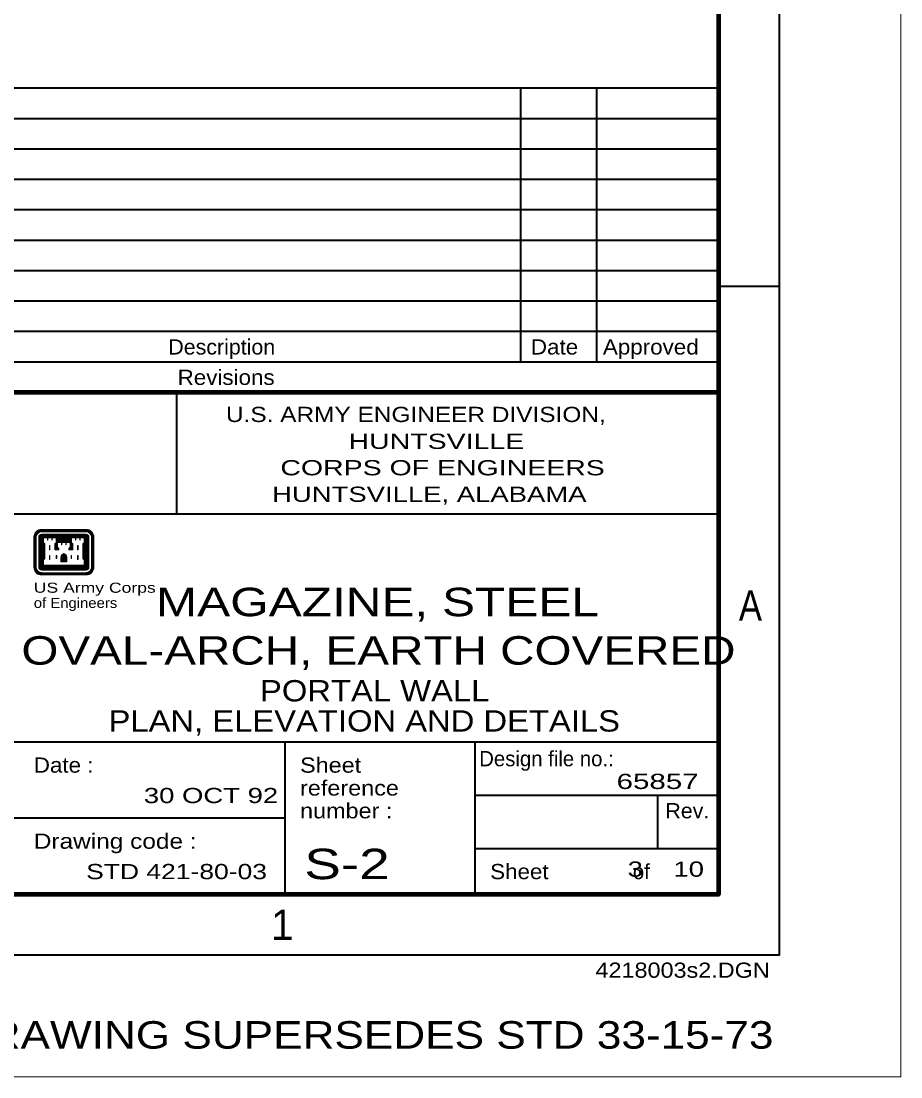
# Model space of a CAD drawing. Extents: x -22.3 to 19.7, y -11.8 to 18.2.
# Drawn here: x 12.46 to 19.69, y -11.84 to -3.16 of the extents above; entities that cross this region are included whole.
import ezdxf
from ezdxf.enums import TextEntityAlignment as Align

# ---------------------------------------------------------------- set-up
doc = ezdxf.new("R2010")
doc.units = 0
doc.header["$LTSCALE"] = 0.05
doc.layers.add('1', color=7, linetype='Continuous', lineweight=13)
doc.layers.add('2', color=7, linetype='Continuous', lineweight=13)

msp = doc.modelspace()

# ---------------------------------------------------------------- linework, layer by layer
at = {"layer": '1', "lineweight": 40}
for p, q in [((18.19058, -3.71469), (10.19058, -3.71469)), ((16.56558, -3.71469), (16.56558, -5.96469)), ((17.19058, -3.71469), (17.19058, -5.96469)), ((18.19058, -3.96469), (10.19058, -3.96469)), ((18.19058, -4.21469), (10.19058, -4.21469)), ((18.19058, -4.46469), (10.19058, -4.46469)), ((18.19058, -4.71469), (10.19058, -4.71469)), ((18.19058, -4.96469), (10.19058, -4.96469)), ((18.19058, -5.21469), (10.19058, -5.21469)), ((18.19058, -5.33969), (18.69058, -5.33969)), ((18.19058, -5.46469), (10.19058, -5.46469)), ((18.19058, -5.71469), (10.19058, -5.71469)), ((18.19058, -5.96469), (10.19058, -5.96469)), ((13.73858, -6.21469), (13.73858, -7.21469)), ((18.19058, -7.21469), (10.19058, -7.21469)), ((18.19058, -9.08969), (10.19058, -9.08969)), ((14.62858, -9.08969), (14.62858, -10.33969)), ((16.19058, -9.08969), (16.19058, -10.33969)), ((18.19058, -9.52769), (16.19058, -9.52769)), ((17.69058, -9.52769), (17.69058, -9.96469)), ((14.62858, -9.71469), (10.19058, -9.71469)), ((18.19058, -9.96469), (16.19058, -9.96469))]:
    msp.add_line(p, q, dxfattribs=at)
at = {"layer": '1', "lineweight": 90}
msp.add_line((18.19058, -6.21469), (10.19058, -6.21469), dxfattribs=at)
at = {"layer": '1'}
for p, q in [((12.99458, -7.33969), (12.63058, -7.33969)), ((12.99458, -7.34369), (12.63058, -7.34369)), ((12.99458, -7.34869), (12.63058, -7.34869)), ((12.99458, -7.35369), (12.63058, -7.35369)), ((12.99458, -7.35969), (12.63058, -7.35969)), ((12.56558, -7.40469), (12.56558, -7.65069)), ((12.56958, -7.40469), (12.56958, -7.65069)), ((12.57558, -7.40469), (12.57558, -7.65069)), ((12.58058, -7.40469), (12.58058, -7.65069)), ((12.58558, -7.40469), (12.58558, -7.65069)), ((12.60658, -7.40469), (12.60658, -7.65069)), ((12.61158, -7.40469), (12.61158, -7.65069)), ((12.61658, -7.40469), (12.61658, -7.65069)), ((12.62158, -7.40469), (12.62158, -7.65069)), ((12.62658, -7.40469), (12.62658, -7.65069)), ((12.99458, -7.37969), (12.63058, -7.37969)), ((12.99458, -7.38569), (12.63058, -7.38569)), ((12.99458, -7.39069), (12.63058, -7.39069)), ((12.99458, -7.39569), (12.63058, -7.39569)), ((12.99458, -7.40069), (12.63058, -7.40069)), ((12.63258, -7.40469), (12.63258, -7.64869)), ((12.63758, -7.40469), (12.63758, -7.64369)), ((12.64158, -7.45669), (12.64158, -7.58269)), ((12.64658, -7.46169), (12.64658, -7.57669)), ((12.75658, -7.40569), (12.86858, -7.40569)), ((12.75658, -7.41069), (12.86858, -7.41069)), ((12.75658, -7.41569), (12.86858, -7.41569)), ((12.75658, -7.42169), (12.86858, -7.42169)), ((12.75658, -7.42669), (12.86858, -7.42669)), ((12.75658, -7.43169), (12.86858, -7.43169)), ((12.75658, -7.43669), (12.86858, -7.43669)), ((12.97858, -7.46169), (12.97858, -7.57669)), ((12.98358, -7.45669), (12.98358, -7.58169)), ((12.98758, -7.40469), (12.98758, -7.64369)), ((12.99258, -7.40469), (12.99258, -7.64869)), ((12.99758, -7.40469), (12.99758, -7.65069)), ((13.00358, -7.40469), (13.00358, -7.65069)), ((13.00858, -7.40469), (13.00858, -7.65069)), ((13.01358, -7.40469), (13.01358, -7.65069)), ((13.01858, -7.40469), (13.01858, -7.65069)), ((13.03958, -7.40469), (13.03958, -7.65069)), ((13.04458, -7.40469), (13.04458, -7.65069)), ((13.05058, -7.40469), (13.05058, -7.65069)), ((13.05558, -7.40469), (13.05558, -7.65069)), ((13.05858, -7.40469), (13.05858, -7.65069)), ((12.78858, -7.60769), (12.78858, -7.56769)), ((12.78858, -7.60769), (12.83658, -7.60769)), ((12.79358, -7.60769), (12.79358, -7.56769)), ((12.79858, -7.60769), (12.79858, -7.56769)), ((12.80358, -7.60769), (12.80358, -7.56769)), ((12.80958, -7.60769), (12.80958, -7.56769)), ((12.81558, -7.60769), (12.81558, -7.56769)), ((12.82058, -7.60769), (12.82058, -7.56769)), ((12.82658, -7.60769), (12.82658, -7.56769)), ((12.83158, -7.60769), (12.83158, -7.56769)), ((12.83658, -7.60769), (12.83658, -7.56769)), ((12.99458, -7.65369), (12.63058, -7.65369)), ((12.99458, -7.65869), (12.63058, -7.65869)), ((12.99458, -7.66469), (12.63058, -7.66469)), ((12.99458, -7.66969), (12.63058, -7.66969)), ((12.99458, -7.67469), (12.63058, -7.67469)), ((12.99458, -7.69569), (12.63058, -7.69569)), ((12.99458, -7.70069), (12.63058, -7.70069)), ((12.99458, -7.70569), (12.63058, -7.70569)), ((12.99458, -7.71169), (12.63058, -7.71169)), ((12.99458, -7.71469), (12.63058, -7.71469)), ((12.99258, -7.64869), (12.63258, -7.64869)), ((12.98758, -7.64369), (12.63758, -7.64369)), ((19.69058, -11.83969), (-22.30942, -11.83969))]:
    msp.add_line(p, q, dxfattribs=at)
for points in [[(-22.30942, 18.16031), (19.69058, 18.16031), (19.69058, -11.83969)], [(12.75058, -7.46169), (12.74758, -7.46469), (12.74758, -7.49869), (12.75858, -7.49869), (12.75158, -7.49069), (12.75158, -7.46069)], [(12.87458, -7.46169), (12.87758, -7.46469), (12.87758, -7.49869), (12.86658, -7.49869), (12.87358, -7.49069), (12.87358, -7.46069)]]:
    msp.add_lwpolyline(points, dxfattribs=at)
at = {"layer": '1', "lineweight": 40}
msp.add_lwpolyline([(-21.30942, -10.83969), (-21.30942, 17.16031), (18.69058, 17.16031), (18.69058, -10.83969)], close=True, dxfattribs=at)
at = {"layer": '1', "lineweight": 90}
msp.add_lwpolyline([(-19.80942, 16.66031), (18.19058, 16.66031), (18.19058, -10.33969), (-19.80942, -10.33969)], close=True, dxfattribs=at)
at = {"layer": '1'}
for points in [[(12.64158, -7.40469), (12.64158, -7.45169), (12.65158, -7.46169), (12.65158, -7.57669), (12.64158, -7.58769), (12.64158, -7.63969), (12.98358, -7.63969), (12.98358, -7.58769), (12.97258, -7.57669), (12.97258, -7.46169), (12.98358, -7.45169), (12.98358, -7.40469), (12.93858, -7.40469), (12.90358, -7.40469), (12.87158, -7.40469), (12.87158, -7.45169), (12.88258, -7.46169), (12.88258, -7.50369), (12.85758, -7.50369), (12.85758, -7.49969), (12.86858, -7.48869), (12.86858, -7.44169), (12.82358, -7.44169), (12.78858, -7.44169), (12.75658, -7.44169), (12.75658, -7.48869), (12.76758, -7.49969), (12.76758, -7.50369), (12.74258, -7.50369), (12.74258, -7.46169), (12.75358, -7.45169), (12.75358, -7.40469), (12.70758, -7.40469), (12.67358, -7.40469)], [(12.64658, -7.40969), (12.64658, -7.44969), (12.65758, -7.45969), (12.65758, -7.57869), (12.64658, -7.58969), (12.64658, -7.63469), (12.97858, -7.63469), (12.97858, -7.58969), (12.96758, -7.57869), (12.96758, -7.45969), (12.97858, -7.44969), (12.97858, -7.40969), (12.94658, -7.40969), (12.94658, -7.42869), (12.94358, -7.42869), (12.94358, -7.40969), (12.91158, -7.40969), (12.91158, -7.42869), (12.90858, -7.42869), (12.90858, -7.40969), (12.87658, -7.40969), (12.87658, -7.44969), (12.88758, -7.45969), (12.88758, -7.50869), (12.85258, -7.50869), (12.85258, -7.49769), (12.86358, -7.48669), (12.86358, -7.44669), (12.83158, -7.44669), (12.83158, -7.46569), (12.82858, -7.46569), (12.82858, -7.44669), (12.79658, -7.44669), (12.79658, -7.46569), (12.79358, -7.46569), (12.79358, -7.44669), (12.76158, -7.44669), (12.76158, -7.48669), (12.77258, -7.49769), (12.77258, -7.50869), (12.73758, -7.50869), (12.73758, -7.45969), (12.74858, -7.44969), (12.74858, -7.40969), (12.71658, -7.40969), (12.71658, -7.42869), (12.71358, -7.42869), (12.71358, -7.40969), (12.68158, -7.40969), (12.68158, -7.42869), (12.67858, -7.42869), (12.67858, -7.40969)], [(12.69558, -7.47369), (12.69558, -7.50869), (12.69858, -7.50869), (12.69858, -7.47369)], [(12.92958, -7.47369), (12.92958, -7.50869), (12.92558, -7.50869), (12.92558, -7.47369)], [(12.69558, -7.55369), (12.69558, -7.58869), (12.69858, -7.58869), (12.69858, -7.55369)], [(12.75058, -7.55369), (12.75058, -7.57869), (12.75358, -7.57869), (12.75358, -7.55369)], [(12.87458, -7.55369), (12.87458, -7.57869), (12.87158, -7.57869), (12.87158, -7.55369)], [(12.92958, -7.55369), (12.92958, -7.58869), (12.92558, -7.58869), (12.92558, -7.55369)]]:
    msp.add_lwpolyline(points, close=True, dxfattribs=at)
for centre, radius, start, end in [((12.63035, -7.40422), 0.06429, 89.99998, 179.99997), ((12.63035, -7.40422), 0.06057, 89.99998, 179.99997), ((12.63035, -7.40422), 0.05536, 89.99998, 179.99997), ((12.63035, -7.40422), 0.05015, 89.99998, 179.99997), ((12.63035, -7.40422), 0.04494, 89.99998, 179.99997), ((12.99464, -7.40422), 0.06429, 359.99998, 89.99998), ((12.99464, -7.40422), 0.06057, 0.00002, 90.00002), ((12.99464, -7.40422), 0.05536, 0.00002, 90.00002), ((12.99464, -7.40422), 0.05015, 0.00002, 90.00002), ((12.99464, -7.40422), 0.04494, 0.00002, 90.00002), ((12.63035, -7.40422), 0.02411, 89.99998, 179.99997), ((12.63035, -7.40422), 0.0189, 89.99998, 179.99997), ((12.63035, -7.40422), 0.01369, 89.99998, 179.99997), ((12.63035, -7.40422), 0.00848, 89.99998, 179.99997), ((12.63035, -7.40422), 0.00327, 89.99998, 179.99997), ((12.99464, -7.40422), 0.02411, 359.99998, 89.99998), ((12.99464, -7.40422), 0.0189, 359.99998, 89.99998), ((12.99464, -7.40422), 0.01369, 359.99998, 89.99998), ((12.99464, -7.40422), 0.00848, 359.99998, 89.99998), ((12.99464, -7.40422), 0.00327, 359.99998, 89.99998), ((12.82147, -7.57026), 0.03332, 105.66805, 176.05748), ((12.82147, -7.57026), 0.02811, 103.46979, 176.05748), ((12.82147, -7.57026), 0.0229, 103.46979, 176.05748), ((12.80352, -7.57026), 0.0229, 3.94252, 76.53021), ((12.80352, -7.57026), 0.02811, 3.94252, 76.53021), ((12.80352, -7.57026), 0.03332, 3.94252, 74.39486), ((12.82147, -7.57026), 0.0177, 103.46979, 176.05748), ((12.80352, -7.57026), 0.01249, 3.94252, 76.53021), ((12.80352, -7.57026), 0.0177, 3.94252, 76.53021), ((12.82147, -7.57026), 0.01249, 103.46979, 176.05748), ((12.63035, -7.65065), 0.06429, 180.00003, 270.00003), ((12.63035, -7.65065), 0.06057, 179.99998, 269.99997), ((12.63035, -7.65065), 0.05536, 179.99998, 269.99997), ((12.63035, -7.65065), 0.05015, 179.99998, 269.99997), ((12.63035, -7.65065), 0.04494, 179.99998, 269.99997), ((12.63035, -7.65065), 0.02411, 180.00003, 270.00003), ((12.63035, -7.65065), 0.0189, 180.00003, 270.00003), ((12.63035, -7.65065), 0.01369, 180.00003, 270.00003), ((12.63035, -7.65065), 0.00848, 180.00003, 270.00003), ((12.63035, -7.65065), 0.00327, 180.00003, 270.00003), ((12.99464, -7.65065), 0.06429, 270.00003, 0.00003), ((12.99464, -7.65065), 0.02411, 270.00003, 0.00003), ((12.99464, -7.65065), 0.0189, 270.00003, 0.00003), ((12.99464, -7.65065), 0.01369, 270.00003, 0.00003), ((12.99464, -7.65065), 0.00848, 270.00003, 0.00003), ((12.99464, -7.65065), 0.00327, 270.00003, 0.00003), ((12.99464, -7.65065), 0.04494, 270.00002, 0.00002), ((12.99464, -7.65065), 0.05015, 270.00002, 0.00002), ((12.99464, -7.65065), 0.05536, 270.00002, 0.00002), ((12.99464, -7.65065), 0.06057, 270.00002, 0.00002)]:
    msp.add_arc(centre, radius, start, end, dxfattribs=at)

# ---------------------------------------------------------------- texts
for s, height, width, p in [('Description', 0.125, 1.05, (14.11008, -5.90269)), ('Date', 0.125, 1.1, (16.84458, -5.90269)), ('Approved', 0.125, 1.1, (17.63558, -5.90269)), ('Revisions', 0.125, 1.1, (14.14608, -6.15269)), ('   U.S. ARMY ENGINEER DIVISION,   ', 0.125, 1.2, (15.70508, -6.45769)), ('           HUNTSVILLE             ', 0.125, 1.4, (15.93858, -6.67869)), ('       CORPS OF ENGINEERS         ', 0.125, 1.4, (15.98958, -6.89569)), ('      HUNTSVILLE, ALABAMA         ', 0.125, 1.35, (15.90958, -7.11369)), ('A', 0.25, 0.85, (18.45408, -8.08969)), ('PORTAL WALL', 0.175, 1.15, (15.36658, -8.75369)), ('PLAN, ELEVATION AND DETAILS', 0.175, 1.15, (15.28108, -9.00169)), ('THIS DRAWING SUPERSEDES STD 33-15-73', 0.226, 1.2, (14.82508, -11.60769))]:
    msp.add_text(s, height=height, dxfattribs=dict(at, width=width)).set_placement(p, align=Align.CENTER)
for s, height, width, p in [('US Army Corps', 0.083, 1.3, (12.56558, -7.86069)), ('of Engineers', 0.083, 1.1, (12.56558, -7.98569)), ('Date :', 0.125, 1.1, (12.56558, -9.33969)), ('Sheet', 0.125, 1.15, (14.75358, -9.33969)), ('reference', 0.125, 1.15, (14.75358, -9.52769)), ('number :', 0.125, 1.15, (14.75358, -9.71469)), ('Rev.', 0.125, 1.05, (17.75558, -9.71469)), ('Drawing code :', 0.125, 1.2, (12.56558, -9.96469)), ('Sheet     ', 0.125, 1.1, (16.31558, -10.21469)), ('4218003s2.DGN', 0.125, 1.15, (17.18114, -11.02502))]:
    msp.add_text(s, height=height, dxfattribs=dict(at, width=width)).set_placement(p)
msp.add_text('Design file no.:', height=0.125, dxfattribs=at).set_placement((16.22558, -9.28669))
msp.add_text('of', height=0.125, dxfattribs=at).set_placement((17.62758, -10.21469), align=Align.RIGHT)
msp.add_text('1', height=0.25, dxfattribs=at).set_placement((14.60758, -10.71469), align=Align.CENTER)
at = {"layer": '2'}
for s, width, p in [('       MAGAZINE, STEEL       ', 1.3, (15.38908, -8.05369)), ('  OVAL-ARCH, EARTH COVERED   ', 1.25, (15.45208, -8.45169))]:
    msp.add_text(s, height=0.234, dxfattribs=dict(at, width=width)).set_placement(p, align=Align.CENTER)
for s, width, p in [('         65857', 1.45, (18.02858, -9.47369)), ('30 OCT 92', 1.35, (14.57358, -9.58969)), ('STD 421-80-03', 1.3, (14.48158, -10.21469)), ('  3    10', 1.35, (18.07258, -10.19469))]:
    msp.add_text(s, height=0.125, dxfattribs=dict(at, width=width)).set_placement(p, align=Align.RIGHT)
at = {"layer": '2', "width": 1.35}
msp.add_text(' S-2  ', height=0.25, dxfattribs=at).set_placement((14.66258, -10.21469))

doc.saveas('drawing.dxf')
